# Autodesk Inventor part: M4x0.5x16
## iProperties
Created: 2009-02
Part Number: M4x0.5x16
Material: 강, 연강
Description: 6각머리 태핑 나사
Document SubType Name: Modeling
Standard: KS B 1003
Designer: 한국산업디자인학원
Standards Organization: KS
Language: ko-KR
Size Designation: M 4 x 16
Categories: <MemberInstance><Categories><Category DisplayName="조임쇠" InternalName="e4da775c-781d-43d5-af7c-5136215cf5a6" Mnemonic="FSTN"><Category DisplayName="볼트" InternalN
Density: 1 g/cm^3
IsCustomPart: 1
Author: 한국산업디자인학원
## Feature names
1. Fillet2
